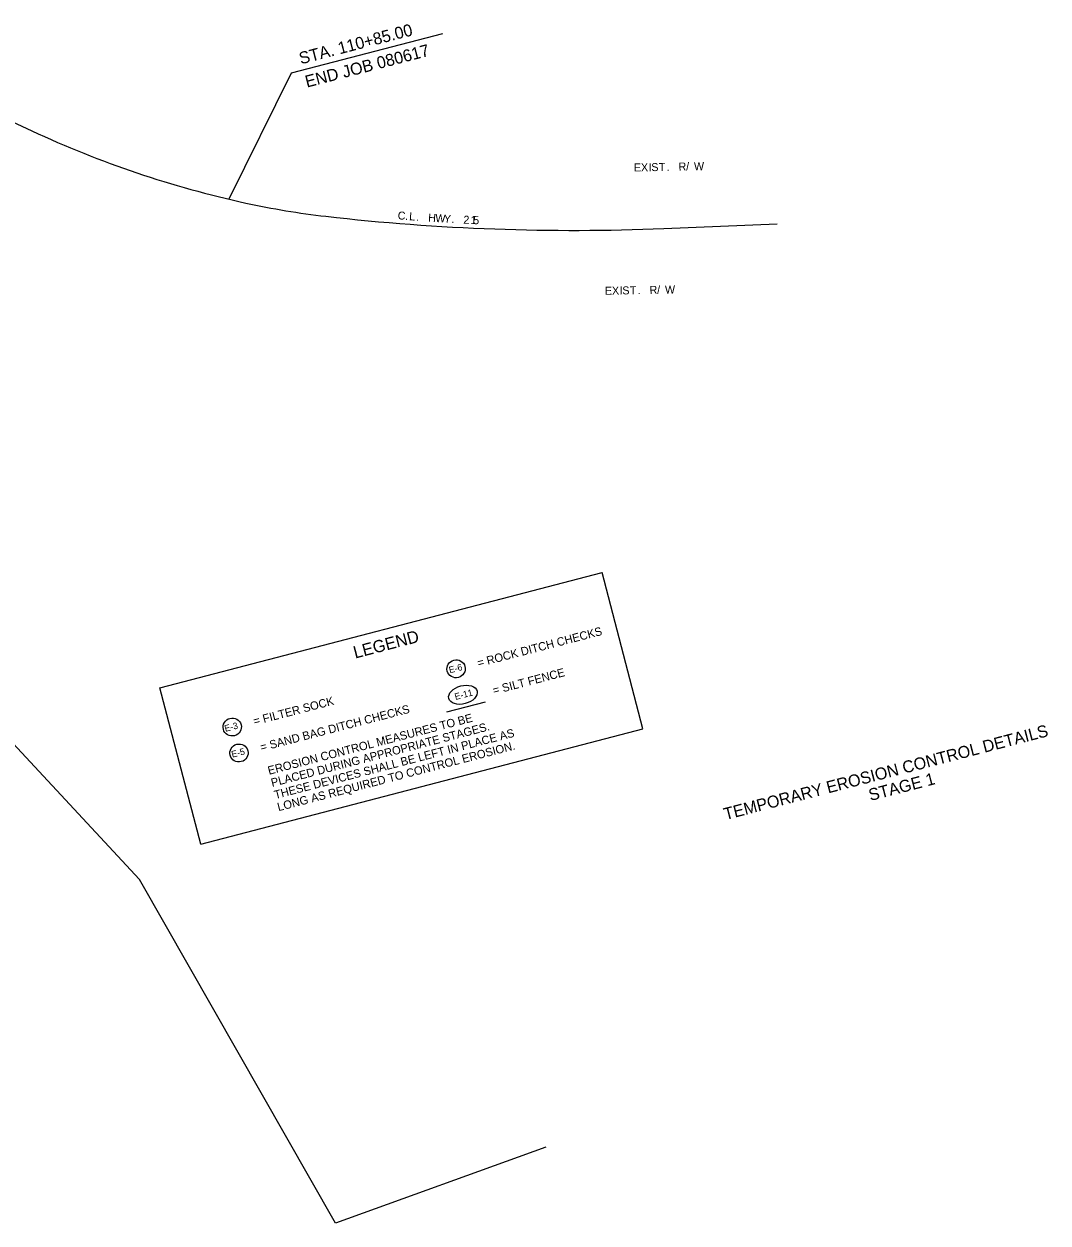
# Model space of a CAD drawing. Extents: x 830993 to 836451, y 495580 to 497751.
# Drawn here: x 835684 to 836451, y 496081 to 496980 of the extents above; entities that cross this region are included whole.
import ezdxf

# ---------------------------------------------------------------- set-up
doc = ezdxf.new("R2010")
doc.units = 0
for name, color, linetype in [('1', 7, 'Continuous'), ('60', 7, 'Continuous'), ('8', 7, 'Continuous'), ('Level 1', 7, 'Continuous'), ('Level 44', 7, 'Continuous'), ('R_Draft', 7, 'Continuous'), ('R_Horz Alg', 7, 'Continuous')]:
    doc.layers.add(name, color=color, linetype=linetype)

msp = doc.modelspace()

# ---------------------------------------------------------------- linework, layer by layer
at = {"layer": '1'}
for p, q in [((835785.51, 496482.52), (836117.07, 496569.03)), ((836147.63, 496451.89), (836117.07, 496569.03)), ((835816.07, 496365.39), (835785.51, 496482.52)), ((835816.07, 496365.39), (836147.63, 496451.89)), ((835816.07, 496365.39), (836147.63, 496451.89))]:
    msp.add_line(p, q, dxfattribs=at)
at = {"layer": '8'}
for p, q in [((835997.36, 496972.87), (835883.78, 496943.36)), ((835883.78, 496943.36), (835837.12, 496848.88))]:
    msp.add_line(p, q, dxfattribs=at)
at = {"layer": 'Level 1'}
for centre, major_axis, ratio in [((836007.53, 496496.86), (-6.66, -1.74), 0.97521), ((836012.69, 496477.37), (10.6, 2.77), 0.622952), ((835839.68, 496453.21), (-6.66, -1.74), 0.97521), ((835844.76, 496433.73), (-6.66, -1.74), 0.97521)]:
    msp.add_ellipse(centre, major_axis=major_axis, ratio=ratio, dxfattribs=at)
at = {"layer": 'Level 44'}
msp.add_lwpolyline([(836000.48, 496464.54), (836029.62, 496472.16)], dxfattribs=at)
at = {"layer": 'R_Draft'}
for points in [[(835770.18, 496338.94), (835570.1, 496553.71), (835173.92, 496666.72)], [(836074.93, 496138.31), (835917.19, 496081.38), (835770.18, 496338.94)]]:
    msp.add_lwpolyline(points, dxfattribs=at)
at = {"layer": 'R_Horz Alg'}
for p, q in [((835657.74, 496914.96), (835689.37, 496900.19)), ((836163.33, 496826.92), (836248.32, 496830.45))]:
    msp.add_line(p, q, dxfattribs=at)
for centre, radius, start, end in [((836012.53, 497592.42), 763.94, 244.975, 257.70667), ((835978.28, 497435.28), 603.11, 257.70667, 263.49722), ((836095.38, 498462.53), 1637.02, 263.49722, 272.37917)]:
    msp.add_arc(centre, radius, start, end, dxfattribs=at)

# ---------------------------------------------------------------- texts
at = {"layer": '60'}
for s, p in [('TEMPORARY EROSION CONTROL DETAILS', (836209.49, 496383.39)), ('STAGE 1', (836318.16, 496397.7))]:
    msp.add_text(s, height=9, rotation=14.57307, dxfattribs=at).set_placement(p)
at = {"layer": '8'}
for s, height, rotation, p in [('STA. 110+85.00', 9, 14.55565, (835891.11, 496949.91)), ('END JOB 080617', 9, 14.55565, (835895.64, 496932.49)), ('E', 6, 1.11413, (836140.82, 496869.64)), ('X', 6, 1.11413, (836146.2, 496869.75)), ('I', 6, 1.11413, (836151.97, 496869.86)), ('S', 6, 1.11413, (836153.95, 496869.9)), ('T', 6, 1.11413, (836159.62, 496870.01)), ('.', 6, 1.11413, (836165.48, 496870.12)), ('R', 6, 1.11413, (836174.4, 496870.3)), ('/', 6, 1.11413, (836180.07, 496870.41)), ('W', 6, 1.11413, (836185.93, 496870.52)), ('C', 6, 355.47291, (835963.58, 496833.83)), ('.', 6, 355.6717, (835969.23, 496833.38)), ('L', 6, 355.77441, (835972.15, 496833.16)), ('.', 6, 355.96326, (835977.52, 496832.76)), ('H', 6, 356.27635, (835986.43, 496832.14)), ('W', 6, 356.4652, (835991.8, 496831.79)), ('Y', 6, 356.69049, (835998.22, 496831.4)), ('.', 6, 356.8926, (836003.97, 496831.07)), ('2', 6, 357.20569, (836012.89, 496830.59)), ('1', 6, 357.39454, (836018.27, 496830.33)), ('5', 6, 357.46412, (836020.25, 496830.24)), ('E', 6, 1.11413, (836119.09, 496777.2)), ('X', 6, 1.11413, (836124.48, 496777.31)), ('I', 6, 1.11413, (836130.24, 496777.42)), ('S', 6, 1.11413, (836132.22, 496777.46)), ('T', 6, 1.11413, (836137.89, 496777.57)), ('.', 6, 1.11413, (836143.75, 496777.68)), ('R', 6, 1.11413, (836152.67, 496777.86)), ('/', 6, 1.11413, (836158.34, 496777.97)), ('W', 6, 1.11413, (836164.2, 496778.08))]:
    msp.add_text(s, height=height, rotation=rotation, dxfattribs=at).set_placement(p)
at = {"layer": 'Level 1'}
for s, height, p in [('= ROCK DITCH CHECKS', 6.25, (836024.32, 496498.01)), ('E-6 ', 4.876, (836002.82, 496493.43)), ('= SILT FENCE', 6.25, (836035.86, 496477.45)), ('= FILTER SOCK', 6.25, (835856.44, 496454.41)), ('E-11 ', 4.876, (836007.11, 496473.44)), ('= SAND BAG DITCH CHECKS', 6.25, (835861.55, 496434.85)), ('E-3 ', 4.876, (835834.55, 496449.58)), ('EROSION CONTROL MEASURES TO BE', 6.25, (835867.25, 496417.36)), ('PLACED DURING APPROPRIATE STAGES. ', 6.25, (835869.63, 496408.26)), ('THESE DEVICES SHALL BE LEFT IN PLACE AS ', 6.25, (835872, 496399.15)), ('E-5 ', 4.876, (835839.75, 496430.22)), ('LONG AS REQUIRED TO CONTROL EROSION.', 6.25, (835874.38, 496390.05))]:
    msp.add_text(s, height=height, rotation=14.62238, dxfattribs=at).set_placement(p)
at = {"layer": 'Level 44'}
msp.add_text('LEGEND', height=9.143, rotation=14.62238, dxfattribs=at).set_placement((835931.85, 496504.47))

doc.saveas('drawing.dxf')
